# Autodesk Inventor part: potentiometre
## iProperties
Author: Administrateur
Created: 2001-04
Part Number: potentiometre
Material: Par défaut
Document SubType Name: Modélisation
Designer: Administrateur
Control State: 0
Master: False
Checked Out: False
PropertySet Name: Design Tracking Control
Shininess: 20.0
PropertySet Name: _Private Model Information
Length Units: 11269
Angle Units: 11283
Time Units: 11279
Mass Units: 11290
Length Display Precision: 3
Angle Display Precision: 2
Compacted: False
Density: 0.0
Volumn: 0.0
Area: 0.0
PropertySet Name: Model Information
